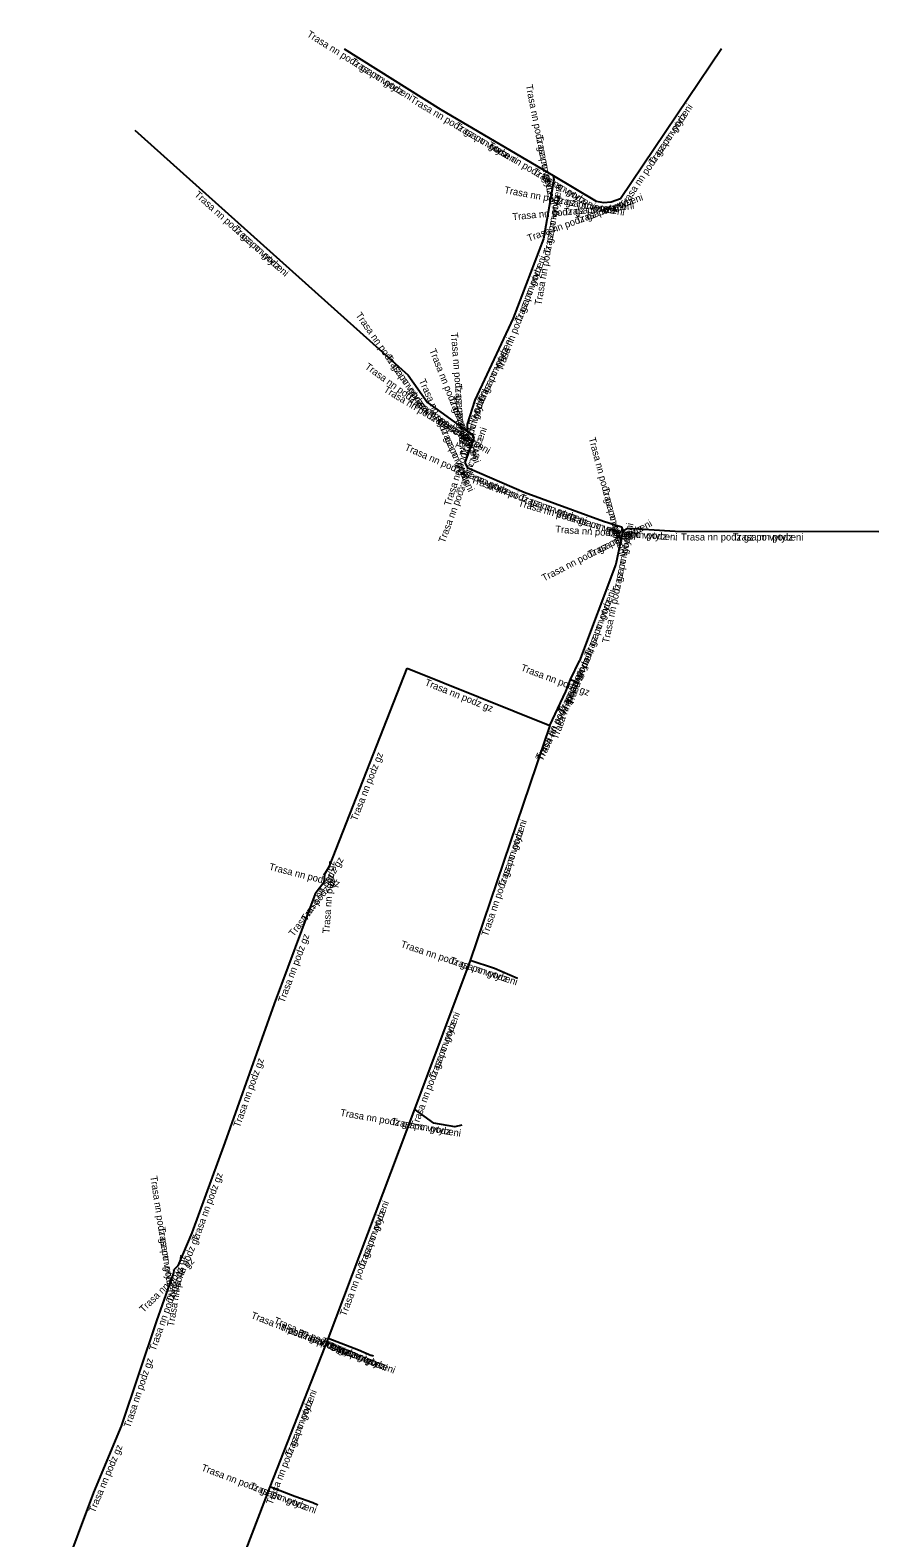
# Model space of a CAD drawing. Extents: x -644332 to -644190, y -1042435 to -1042173.
# Drawn here: x -644249.9 to -644189.5, y -1042279.6 to -1042172.5 of the extents above; entities that cross this region are included whole.
import ezdxf

# ---------------------------------------------------------------- set-up
doc = ezdxf.new("R2010")
doc.units = 0
doc.layers.add('Popiskový text - Ostatní atributy Trasy', color=7, linetype='Continuous')
doc.layers.add('Spojnice NN', color=7, linetype='Continuous')

msp = doc.modelspace()

# ---------------------------------------------------------------- linework, layer by layer
at = {"layer": 'Spojnice NN'}
for points in [[(-644227.53, -1042173.85), (-644220.65, -1042178.14)], [(-644227.53, -1042173.85), (-644220.65, -1042178.14)], [(-644207.88, -1042184.48), (-644200.71, -1042173.82)], [(-644207.88, -1042184.48), (-644200.71, -1042173.82)], [(-644220.65, -1042178.14), (-644212.68, -1042182.85)], [(-644220.65, -1042178.14), (-644212.68, -1042182.85)], [(-644242.42, -1042179.63), (-644222.97, -1042197.02)], [(-644242.42, -1042179.63), (-644222.97, -1042197.02)], [(-644212.62, -1042183.15), (-644213.35, -1042187.35)], [(-644212.62, -1042183.15), (-644213.35, -1042187.35)], [(-644212.68, -1042182.85), (-644209.61, -1042184.67)], [(-644212.68, -1042182.85), (-644212.62, -1042183.15)], [(-644212.68, -1042182.85), (-644212.62, -1042183.15)], [(-644212.68, -1042182.85), (-644209.61, -1042184.67)], [(-644209.61, -1042184.67), (-644209.08, -1042184.77)], [(-644209.61, -1042184.67), (-644209.08, -1042184.77)], [(-644209.08, -1042184.77), (-644208.54, -1042184.72)], [(-644209.08, -1042184.77), (-644208.54, -1042184.72)], [(-644208.54, -1042184.72), (-644207.88, -1042184.48)], [(-644208.54, -1042184.72), (-644207.88, -1042184.48)], [(-644213.35, -1042187.35), (-644215.52, -1042192.98)], [(-644213.35, -1042187.35), (-644215.52, -1042192.98)], [(-644215.52, -1042192.98), (-644218.25, -1042198.81)], [(-644215.52, -1042192.98), (-644218.25, -1042198.81)], [(-644222.97, -1042197.02), (-644221.61, -1042198.96)], [(-644222.97, -1042197.02), (-644221.61, -1042198.96)], [(-644221.61, -1042198.96), (-644218.75, -1042201.03)], [(-644221.61, -1042198.96), (-644218.75, -1042201.03)], [(-644218.25, -1042198.81), (-644218.79, -1042200.51)], [(-644218.25, -1042198.81), (-644218.79, -1042200.51)], [(-644218.79, -1042200.51), (-644218.75, -1042201.03)], [(-644218.79, -1042200.51), (-644218.75, -1042201.03)], [(-644218.75, -1042201.03), (-644218.4, -1042201.24)], [(-644218.75, -1042201.03), (-644218.4, -1042201.24)], [(-644218.4, -1042201.24), (-644218.3, -1042201.49)], [(-644218.4, -1042201.24), (-644218.3, -1042201.49)], [(-644218.3, -1042201.49), (-644218.94, -1042203.22)], [(-644218.3, -1042201.49), (-644218.94, -1042203.22)], [(-644218.94, -1042203.22), (-644218.78, -1042203.58)], [(-644218.94, -1042203.22), (-644218.78, -1042203.58)], [(-644218.78, -1042203.58), (-644214.72, -1042205.35)], [(-644218.78, -1042203.58), (-644214.72, -1042205.35)], [(-644214.72, -1042205.35), (-644209.1, -1042207.41)], [(-644214.72, -1042205.35), (-644209.1, -1042207.41)], [(-644209.1, -1042207.41), (-644207.8, -1042207.79)], [(-644209.1, -1042207.41), (-644207.8, -1042207.79)], [(-644207.8, -1042207.79), (-644207.72, -1042208.09)], [(-644207.8, -1042207.79), (-644207.72, -1042208.09)], [(-644207.72, -1042208.09), (-644207.35, -1042207.9)], [(-644207.72, -1042208.09), (-644207.35, -1042207.9)], [(-644207.35, -1042207.9), (-644203.99, -1042208.12)], [(-644207.35, -1042207.9), (-644203.99, -1042208.12)], [(-644207.72, -1042208.09), (-644208.21, -1042210.46)], [(-644207.72, -1042208.09), (-644208.21, -1042210.46)], [(-644203.99, -1042208.12), (-644189.51, -1042208.13)], [(-644203.99, -1042208.12), (-644189.51, -1042208.13)], [(-644208.21, -1042210.46), (-644210.79, -1042217.31)], [(-644208.21, -1042210.46), (-644210.79, -1042217.31)], [(-644211.44, -1042218.65), (-644210.79, -1042217.31)], [(-644211.44, -1042218.65), (-644210.79, -1042217.31)], [(-644228.57, -1042231.9), (-644223.05, -1042217.85)], [(-644223.05, -1042217.85), (-644212.91, -1042221.92)], [(-644212.91, -1042221.92), (-644211.76, -1042219.5)], [(-644211.76, -1042219.5), (-644211.44, -1042218.65)], [(-644211.44, -1042218.65), (-644210.83, -1042218.88)], [(-644212.91, -1042221.92), (-644218.57, -1042238.61)], [(-644212.91, -1042221.92), (-644218.57, -1042238.61)], [(-644228.93, -1042232.5), (-644229.01, -1042232.48)], [(-644228.93, -1042232.5), (-644228.97, -1042233.06)], [(-644228.93, -1042232.5), (-644228.57, -1042231.9)], [(-644228.97, -1042233.06), (-644229.59, -1042233.87)], [(-644229.59, -1042233.87), (-644232.5, -1042241.69)], [(-644218.57, -1042238.61), (-644222.53, -1042249.17)], [(-644218.57, -1042238.61), (-644222.53, -1042249.17)], [(-644215.2, -1042239.9), (-644216.85, -1042239.18), (-644218.57, -1042238.61)], [(-644215.2, -1042239.9), (-644216.85, -1042239.18), (-644218.57, -1042238.61)], [(-644232.5, -1042241.69), (-644236.02, -1042251.55)], [(-644222.53, -1042249.17), (-644228.67, -1042265.44)], [(-644222.53, -1042249.17), (-644228.67, -1042265.44)], [(-644219.17, -1042250.31), (-644219.67, -1042250.42), (-644221.15, -1042250.16), (-644222.53, -1042249.17)], [(-644219.17, -1042250.31), (-644219.67, -1042250.42), (-644221.15, -1042250.16), (-644222.53, -1042249.17)], [(-644236.02, -1042251.55), (-644238.37, -1042257.95)], [(-644238.37, -1042257.95), (-644239.35, -1042260.31)], [(-644239.35, -1042260.31), (-644239.64, -1042260.59)], [(-644239.66, -1042260.79), (-644240.87, -1042264.21)], [(-644239.63, -1042260.62), (-644239.66, -1042260.79)], [(-644239.63, -1042260.62), (-644239.64, -1042260.59)], [(-644239.63, -1042260.62), (-644239.64, -1042260.59)], [(-644240.87, -1042264.21), (-644243.38, -1042271.7)], [(-644228.67, -1042265.44), (-644232.82, -1042276)], [(-644228.67, -1042265.44), (-644232.82, -1042276)], [(-644228.67, -1042265.44), (-644226.51, -1042266.27)], [(-644228.67, -1042265.44), (-644226.51, -1042266.27)], [(-644226.51, -1042266.27), (-644225.58, -1042266.67)], [(-644226.51, -1042266.27), (-644225.58, -1042266.67)], [(-644225.44, -1042266.72), (-644225.58, -1042266.67)], [(-644225.44, -1042266.72), (-644225.58, -1042266.67)], [(-644243.38, -1042271.7), (-644245.35, -1042276.4)], [(-644245.35, -1042276.4), (-644249.86, -1042288.43)], [(-644232.82, -1042276), (-644241.24, -1042297.96)], [(-644232.82, -1042276), (-644241.24, -1042297.96)], [(-644229.41, -1042277.31), (-644229.76, -1042277.14), (-644231.03, -1042276.68), (-644232.82, -1042276)], [(-644229.41, -1042277.31), (-644229.76, -1042277.14), (-644231.03, -1042276.68), (-644232.82, -1042276)]]:
    msp.add_lwpolyline(points, dxfattribs=at)

# ---------------------------------------------------------------- texts
at = {"layer": 'Popiskový text - Ostatní atributy Trasy'}
for s, rotation, p in [('Trasa nn podz gz po vytyceni', 328.0545, (-644230.23, -1042172.93)), ('Trasa nn podz', 328.0545, (-644227.11, -1042174.88)), ('Trasa nn podz gz po vytyceni', 281.3099, (-644214.63, -1042176.43)), ('Trasa nn podz gz po vytyceni', 329.4184, (-644222.88, -1042177.58)), ('Trasa nn podz gz po vytyceni', 56.0749, (-644207.57, -1042185.18)), ('Trasa nn podz', 56.0749, (-644205.51, -1042182.12)), ('Trasa nn podz', 329.4184, (-644219.71, -1042179.45)), ('Trasa nn podz', 281.3099, (-644213.9, -1042180.04)), ('Trasa nn podz gz po vytyceni', 329.3391, (-644217.35, -1042180.83)), ('Trasa nn podz', 329.3391, (-644214.18, -1042182.71)), ('Trasa nn podz gz po vytyceni', 318.2005, (-644238.22, -1042184.26)), ('Trasa nn podz gz po vytyceni', 349.3151, (-644216.18, -1042184.09)), ('Trasa nn podz gz po vytyceni', 19.9831, (-644214.41, -1042187.55)), ('Trasa nn podz gz po vytyceni', 80.14, (-644213.51, -1042192.09)), ('Trasa nn podz', 80.14, (-644212.88, -1042188.46)), ('Trasa nn podz', 349.3151, (-644212.56, -1042184.78)), ('Trasa nn podz gz po vytyceni', 5.2901, (-644215.55, -1042186.02)), ('Trasa nn podz', 5.2901, (-644211.88, -1042185.68)), ('Trasa nn podz', 19.9831, (-644210.95, -1042186.29)), ('Trasa nn podz', 318.2005, (-644235.48, -1042186.71)), ('Trasa nn podz gz po vytyceni', 68.9216, (-644216.29, -1042196.77)), ('Trasa nn podz', 68.9216, (-644214.96, -1042193.34)), ('Trasa nn podz gz po vytyceni', 305.0316, (-644226.74, -1042192.77)), ('Trasa nn podz gz po vytyceni', 274.3987, (-644219.94, -1042194.01)), ('Trasa nn podz gz po vytyceni', 64.9078, (-644219.19, -1042202.36)), ('Trasa nn podz', 64.9078, (-644217.63, -1042199.02)), ('Trasa nn podz gz po vytyceni', 324.1039, (-644226.1, -1042196.52)), ('Trasa nn podz', 305.0316, (-644224.63, -1042195.79)), ('Trasa nn podz gz po vytyceni', 291.8014, (-644221.49, -1042195.26)), ('Trasa nn podz gz po vytyceni', 329.0362, (-644224.77, -1042198.18)), ('Trasa nn podz gz po vytyceni', 293.9625, (-644222.23, -1042197.42)), ('Trasa nn podz gz po vytyceni', 72.3777, (-644219.97, -1042206.37)), ('Trasa nn podz', 274.3987, (-644219.66, -1042197.68)), ('Trasa nn podz', 324.1039, (-644223.11, -1042198.68)), ('Trasa nn podz', 291.8014, (-644220.12, -1042198.68)), ('Trasa nn podz', 72.3777, (-644218.85, -1042202.86)), ('Trasa nn podz', 329.0362, (-644221.61, -1042200.07)), ('Trasa nn podz gz po vytyceni', 69.6984, (-644220.38, -1042208.99)), ('Trasa nn podz', 293.9625, (-644220.73, -1042200.79)), ('Trasa nn podz', 69.6984, (-644219.1, -1042205.53)), ('Trasa nn podz gz po vytyceni', 284.9314, (-644210.15, -1042201.51)), ('Trasa nn podz gz po vytyceni', 336.4447, (-644223.27, -1042202.33)), ('Trasa nn podz', 336.4447, (-644219.9, -1042203.8)), ('Trasa nn podz gz po vytyceni', 339.8697, (-644218.55, -1042204.64)), ('Trasa nn podz', 339.8697, (-644215.09, -1042205.91)), ('Trasa nn podz', 284.9314, (-644209.2, -1042205.07)), ('Trasa nn podz gz po vytyceni', 343.706, (-644215.19, -1042206.31)), ('Trasa nn podz gz po vytyceni', 27.1811, (-644213.32, -1042211.69)), ('Trasa nn podz gz po vytyceni', 356.2538, (-644212.53, -1042208.21)), ('Trasa nn podz', 343.706, (-644211.65, -1042207.34)), ('Trasa nn podz', 27.1811, (-644210.04, -1042210.01)), ('Trasa nn podz gz po vytyceni', 78.3186, (-644208.71, -1042216.1)), ('Trasa nn podz', 356.2538, (-644208.85, -1042208.45)), ('Trasa nn podz', 78.3186, (-644207.97, -1042212.49)), ('Trasa nn podz gz po vytyceni', 359.9604, (-644203.58, -1042208.77)), ('Trasa nn podz', 359.9604, (-644199.9, -1042208.77)), ('Trasa nn podz gz po vytyceni', 69.3615, (-644211.3, -1042220.51)), ('Trasa nn podz', 69.3615, (-644210, -1042217.06)), ('Trasa nn podz gz po vytyceni', 64.1232, (-644213.51, -1042224.41)), ('Trasa nn podz gz', 339.3721, (-644215.01, -1042218)), ('Trasa nn podz', 64.1232, (-644211.9, -1042221.1)), ('Trasa nn podz gz', 338.1304, (-644221.84, -1042219.04)), ('Trasa nn podz gz', 69.5182, (-644212.35, -1042222.95)), ('Trasa nn podz gz', 64.5422, (-644213.42, -1042224.5)), ('Trasa nn podz gz', 68.551, (-644226.63, -1042228.74)), ('Trasa nn podz gz po vytyceni', 71.2669, (-644217.32, -1042236.94)), ('Trasa nn podz', 71.2669, (-644216.14, -1042233.45)), ('Trasa nn podz gz', 59.0362, (-644230.2, -1042235.87)), ('Trasa nn podz gz', 345.8014, (-644232.91, -1042232.16)), ('Trasa nn podz gz', 85.9144, (-644228.58, -1042236.71)), ('Trasa nn podz gz', 52.5684, (-644231.13, -1042236.95)), ('Trasa nn podz gz', 69.5886, (-644231.79, -1042241.66)), ('Trasa nn podz gz po vytyceni', 341.665, (-644223.55, -1042237.65)), ('Trasa nn podz', 341.665, (-644220.05, -1042238.81)), ('Trasa nn podz gz po vytyceni', 69.444, (-644222.34, -1042250.52)), ('Trasa nn podz', 69.444, (-644221.05, -1042247.07)), ('Trasa nn podz gz', 70.3535, (-644234.96, -1042250.51)), ('Trasa nn podz gz po vytyceni', 350.0362, (-644227.84, -1042249.64)), ('Trasa nn podz', 350.0362, (-644224.21, -1042250.28)), ('Trasa nn podz gz po vytyceni', 278.7462, (-644241.32, -1042253.95)), ('Trasa nn podz gz', 69.8374, (-644237.93, -1042258.63)), ('Trasa nn podz gz po vytyceni', 69.3244, (-644227.4, -1042263.93)), ('Trasa nn podz', 69.3244, (-644226.1, -1042260.48)), ('Trasa nn podz', 278.7462, (-644240.75, -1042257.59)), ('Trasa nn podz gz', 67.4491, (-644239.75, -1042262.97)), ('Trasa nn podz gz', 44.799, (-644241.8, -1042263.66)), ('Trasa nn podz gz', 80.647, (-644239.64, -1042264.65)), ('Trasa nn podz gz', 70.5162, (-644240.95, -1042266.39)), ('Trasa nn podz gz po vytyceni', 338.9803, (-644234.2, -1042264.01)), ('Trasa nn podz gz po vytyceni', 336.7271, (-644232.58, -1042264.37)), ('Trasa nn podz gz po vytyceni', 339.0755, (-644232.13, -1042264.86)), ('Trasa nn podz', 338.9803, (-644230.76, -1042265.33)), ('Trasa nn podz', 336.7271, (-644229.19, -1042265.82)), ('Trasa nn podz', 339.0755, (-644228.68, -1042266.18)), ('Trasa nn podz gz', 71.4733, (-644242.75, -1042271.85)), ('Trasa nn podz gz po vytyceni', 68.5455, (-644232.64, -1042277.32)), ('Trasa nn podz', 68.5455, (-644231.29, -1042273.89)), ('Trasa nn podz gz', 67.2591, (-644245.27, -1042277.89)), ('Trasa nn podz gz po vytyceni', 339.1988, (-644237.73, -1042274.83)), ('Trasa nn podz', 339.1988, (-644234.29, -1042276.14))]:
    msp.add_text(s, height=0.5, rotation=rotation, dxfattribs=at).set_placement(p)

doc.saveas('drawing.dxf')
